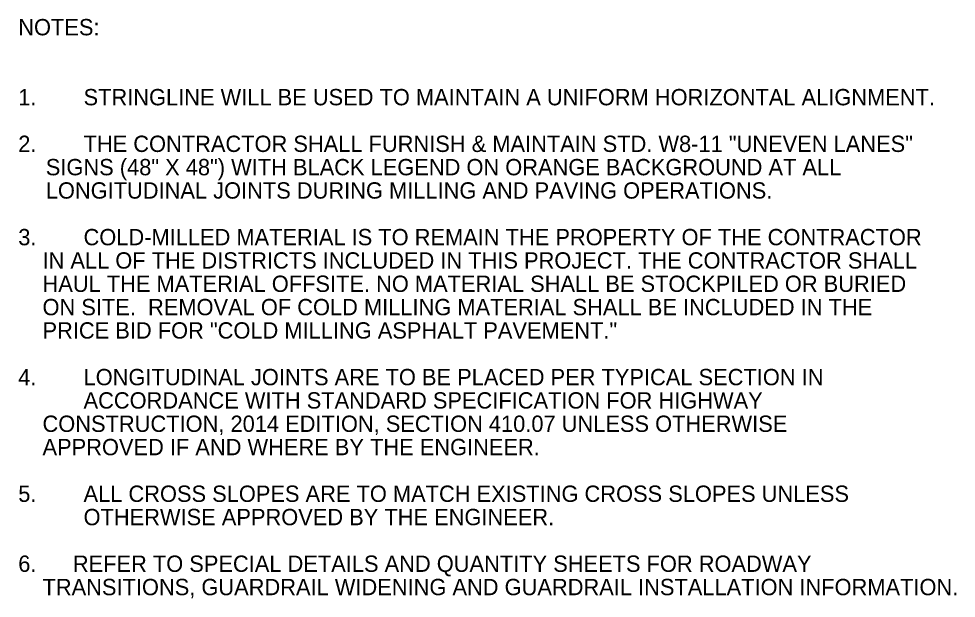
# Model space of a CAD drawing. Extents: x 544199 to 1930787, y -1968972 to 596640.
# Drawn here: x 551001.2 to 551403.2, y -1958705.2 to -1958456.8 of the extents above; entities that cross this region are included whole.
import ezdxf

# ---------------------------------------------------------------- set-up
doc = ezdxf.new("R2010")
doc.units = 0
doc.layers.add('R_Border Notes', color=7, linetype='Continuous')

msp = doc.modelspace()

# ---------------------------------------------------------------- texts
at = {"layer": 'R_Border Notes'}
for s, p in [('NOTES: ', (551000.98, -1958463.91)), ('1.', (551000.98, -1958493.91)), ('STRINGLINE WILL BE USED TO MAINTAIN A UNIFORM HORIZONTAL ALIGNMENT.', (551028.98, -1958493.91)), ('2.', (551000.98, -1958513.91)), ('THE CONTRACTOR SHALL FURNISH & MAINTAIN STD. W8-11 "UNEVEN LANES" ', (551028.98, -1958513.91)), ('    SIGNS (48" X 48") WITH BLACK LEGEND ON ORANGE BACKGROUND AT ALL ', (551002.38, -1958523.91)), ('    LONGITUDINAL JOINTS DURING MILLING AND PAVING OPERATIONS.', (551002.38, -1958533.91)), ('3.', (551000.98, -1958553.91)), ('COLD-MILLED MATERIAL IS TO REMAIN THE PROPERTY OF THE CONTRACTOR', (551028.98, -1958553.91)), ('    IN ALL OF THE DISTRICTS INCLUDED IN THIS PROJECT. THE CONTRACTOR SHALL', (551000.98, -1958563.91)), ('    HAUL THE MATERIAL OFFSITE. NO MATERIAL SHALL BE STOCKPILED OR BURIED', (551000.98, -1958573.91)), ('    ON SITE.  REMOVAL OF COLD MILLING MATERIAL SHALL BE INCLUDED IN THE', (551000.98, -1958583.91)), ('    PRICE BID FOR "COLD MILLING ASPHALT PAVEMENT."', (551000.98, -1958593.91)), ('4.', (551000.98, -1958613.91)), ('LONGITUDINAL JOINTS ARE TO BE PLACED PER TYPICAL SECTION IN ', (551028.98, -1958613.91)), ('ACCORDANCE WITH STANDARD SPECIFICATION FOR HIGHWAY', (551028.98, -1958623.91)), ('    CONSTRUCTION, 2014 EDITION, SECTION 410.07 UNLESS OTHERWISE', (551000.98, -1958633.91)), ('    APPROVED IF AND WHERE BY THE ENGINEER.', (551000.98, -1958643.91)), ('5.', (551000.98, -1958663.91)), ('ALL CROSS SLOPES ARE TO MATCH EXISTING CROSS SLOPES UNLESS ', (551028.98, -1958663.91)), ('OTHERWISE APPROVED BY THE ENGINEER.', (551028.98, -1958673.91)), ('6.      REFER TO SPECIAL DETAILS AND QUANTITY SHEETS FOR ROADWAY', (551000.98, -1958693.91)), ('    TRANSITIONS, GUARDRAIL WIDENING AND GUARDRAIL INSTALLATION INFORMATION.', (551000.98, -1958703.91))]:
    msp.add_text(s, height=7, dxfattribs=at).set_placement(p)

doc.saveas('drawing.dxf')
